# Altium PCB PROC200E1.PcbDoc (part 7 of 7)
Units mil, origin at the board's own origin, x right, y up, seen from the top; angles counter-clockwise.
Board outline 4163.97 x 3505.34 mil, 6 copper layers (Top Layer, GND1, SIG1, PWR, GND2, Bottom), stack 58.132 mil thick; 367 components, 387 nets, 1784 pads, 858 vias.
Unrouted connection lines stored in the file: 17.
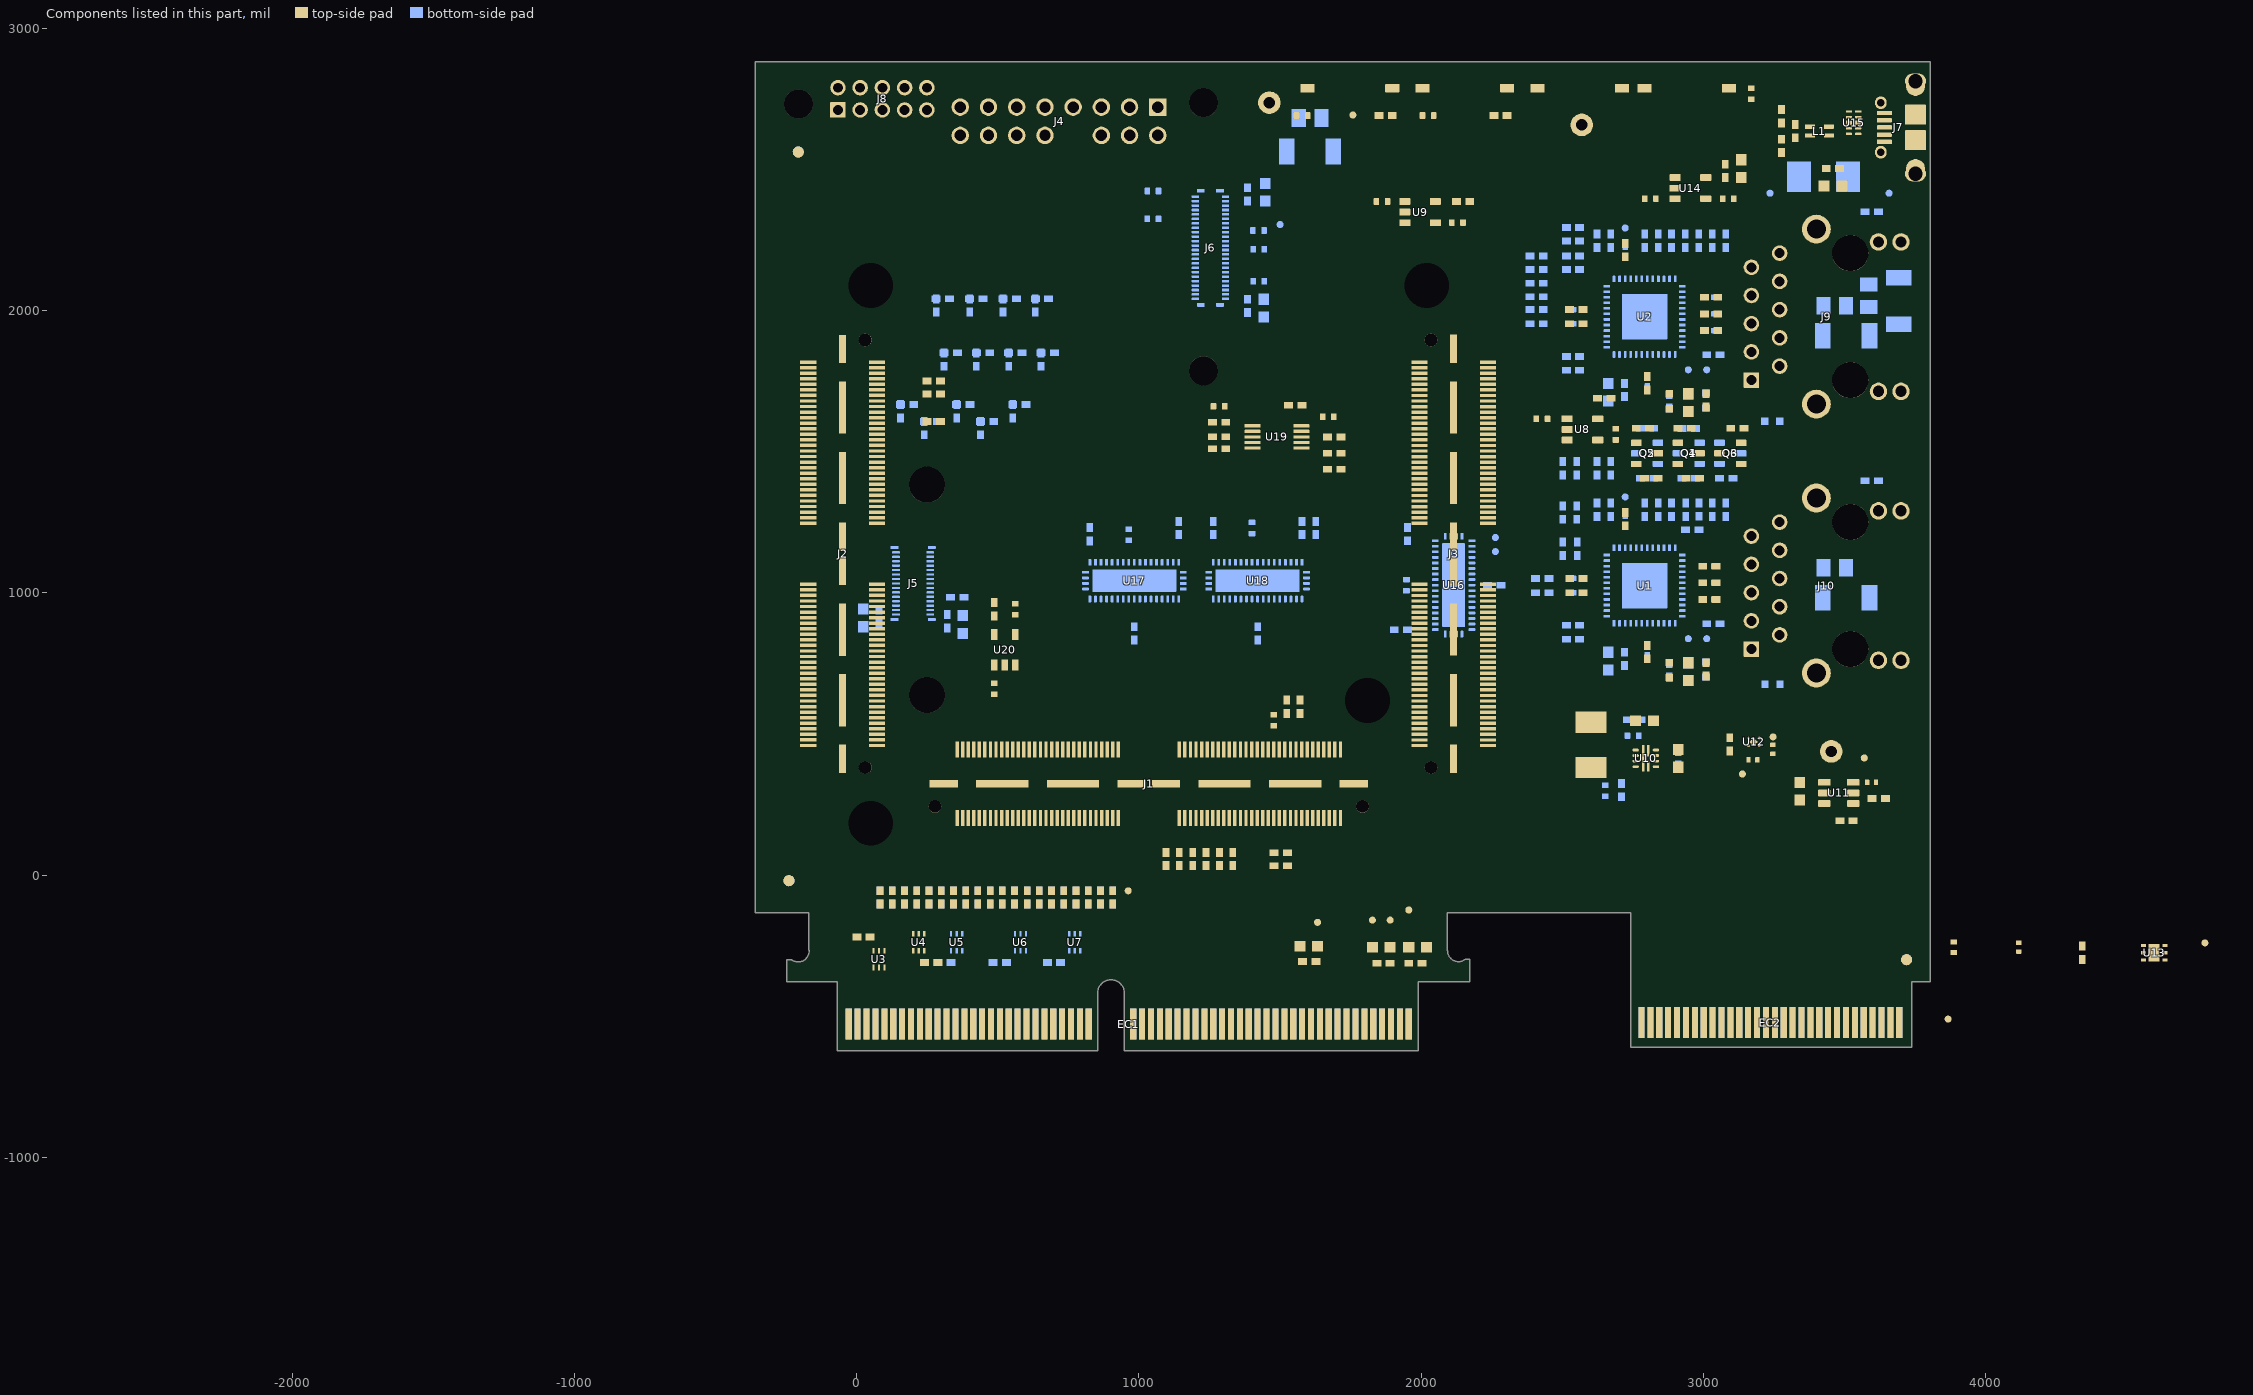
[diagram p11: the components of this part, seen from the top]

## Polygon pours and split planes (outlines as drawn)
GND on PWR "PWR_GND_P156" (solid, remove dead copper, pour order 156): 853.8,-555.76 853.8,-418.09 853.9,-418.09 cw(c901.05,-418.09) 948.19,-418.09 948.29,-418.09 948.29,-550.72 1989.24,-550.72 1989.23,-377.97 2171.95,-377.97 2171.95,-298.97 2155.95,-298.97 cw(c2132.45,-267.85) 2093.45,-267.97 2092.95,-267.97 2092.95,-133.97 2743.26,-133.97 2743.26,-550.72 3738.54,-550.72 3738.54,-377.87 3803.95,-377.87 3803.95,2882.53 -360.02,2882.53 -360.02,-133.97 -169.05,-133.97 -169.05,-266.97 -168.55,-266.95 cw(c-207.5,-268.88) -231.05,-299.97 -247.05,-299.97 -247.05,-377.97 -68.64,-377.97 -68.64,-555.76
VDD_ETH_2V5 on PWR "PWR_VDD_ETH_2V5_P097" (solid, remove dead copper, pour order 97): 2900.95,584.81 2796.86,480.72 2258.57,480.72 2258.57,1196 1817,1196 1817,1934.06 1469,1934.06 1469,2068.71 2114,2068.71 2114,1958.99 2114,1393 2432.71,1393 2432.71,619.35 2865.14,619.35 2865.14,681.93 2900.95,681.93
VMAIN_5V0_IN on PWR "PWR Layer 4-5V0_IN" (solid, remove dead copper, pour order 140): 1828.81,-250.32 1828.81,-128.93 1919.74,-38 2302.9,-38 2777,-38 2777,-450 3711.31,-450 3711.31,-357.25 3731.03,-337.53 3763.61,-337.53 3763.61,2449.57 3724.18,2489 3178,2489 3170,2481 3170,2411 3202.77,2378.23 3738.12,2378.23 3738.12,-202.88 3119.71,-202.88 3119.71,447 2927.37,447 2927.37,380.61 2894.21,347.44 2845.44,347.44 2749.93,251.93 2134.94,251.93 2134.94,798.41 1490,798.41 1490,15 1000,15 558.35,15 558.35,-436.88 727.21,-436.88 727.21,-323.31 692.25,-288.34 692.25,-220 1359.38,-220 1359.38,-462.63 1388.1,-462.63 1388.1,-357.25 1578.89,-357.25 1578.89,-462.64 1608.36,-462.64 1608.36,-357.25 1726.41,-357.25 1795.78,-426.61 1795.78,-462.64 1828.81,-462.64
3V3_LDO2 on PWR "3V3_LDO2_L08_P-001" (solid, remove dead copper, pour order 141): 2795.42,479.28 2900.95,584.81 2900.95,604.05 2916.25,619.35 3101.38,619.35 3305.09,415.64 3305.09,331.82 3299.11,325.84 3135,325.84 3135,443.19 3115.36,462.82 3114.83,462.29 2927.37,462.29 2912.08,447 2912.08,391.63 2883.18,362.73 2839.11,362.73 2738.99,262.62 2123.04,262.62 2123.04,798.14 1475,798.14 1475,512 1384.15,512 1384.15,742 534.08,742 534.08,624 467.49,624 467.49,742 14.72,742 14.72,-177 633.95,-177 633.95,-451.58 713.13,-451.58 713.13,-235.72 964.72,-235.72 1359,-235.72 1359,-478 1862,-478 1862,-99.81 2060.3,-99.81 2060.3,-355.15 1969.72,-355.15 1969.72,-550.72 988.63,-550.72 988.63,-353.09 813.55,-353.09 813.55,-555.76 -68.64,-555.76 -68.64,-393.64 -68.64,-378 -168.55,-378 -168.55,-133.97 -280.28,-133.97 -280.28,479.28 -277.35,482.2 -277.35,978 783,978 783,2382.59 -360.02,2382.59 -360.02,2882.53 3803.95,2882.53 3803.95,2386.29 2327.43,2386.29 2327.43,2073.04 2432.71,2073.04 2432.71,1408.29 2295,1408.29 2295,479.28 2744.36,479.28
VDDIO_3V3 on PWR "VDDIO_3V3_L08_P-001" (solid, remove dead copper, pour order 147): 2338.95,2371 2338.95,2084 2448,2084 2448,634.64 3107.71,634.64 3423.36,319 3713.68,319 3713.68,2371
VBUS_MICRO_AB_5V0 on PWR "PWR-VBUS_MICRO_AB_5V0" (solid, remove dead copper, pour order 130): 3149.78,2608 3187.67,2570.11 3241.84,2570.11 3279.72,2608 3803.95,2608 3803.95,2421 3519,2421 3519,2500 2937,2500 2937,2554 2991,2608
GND on GND1 "GND1_GND_P144" (solid, remove dead copper, pour order 144): 853.8,-555.76 853.8,-418.09 853.9,-418.09 cw(c901.05,-418.09) 948.19,-418.09 948.29,-418.09 948.29,-550.72 1989.24,-550.72 1989.23,-377.97 2171.95,-377.97 2171.95,-298.97 2155.95,-298.97 cw(c2132.45,-267.85) 2093.45,-267.97 2092.95,-267.97 2092.95,-133.97 2743.26,-133.97 2743.26,-550.72 3738.54,-550.72 3738.54,-377.87 3803.95,-377.87 3803.95,2882.53 -360.02,2882.53 -360.02,-133.97 -169.05,-133.97 -169.05,-266.97 -168.55,-266.95 cw(c-207.5,-268.88) -231.05,-299.97 -247.05,-299.97 -247.05,-377.97 -68.64,-377.97 -68.64,-555.76
SHIELD5 on GND1 "GND1_SHIELD5_P142" (solid, remove dead copper, pour order 142): 1625.66,2839.7 1625.66,2516 1747,2516 1747,2668 1849.27,2770.27 3554.37,2770.27 3608.08,2709 3608.08,2066 3803.95,2066 3803.95,2839.7
SHIELD2 on GND1 "GND1_SHIELD2_P143" (solid, remove dead copper, pour order 143): 3349.03,2339.71 3349.03,664.52 3451.39,664.52 3451.39,2339.71
GND on Top Layer "TOP_LAYER_GND_P164" (solid, remove dead copper, pour order 164): 853.8,-555.76 853.8,-418.09 853.9,-418.09 cw(c901.05,-418.09) 948.19,-418.09 948.29,-418.09 948.29,-550.72 1989.24,-550.72 1989.23,-377.97 2171.95,-377.97 2171.95,-298.97 2155.95,-298.97 cw(c2132.45,-267.85) 2093.45,-267.97 2092.95,-267.97 2092.95,-133.97 2743.26,-133.97 2743.26,-550.72 3738.54,-550.72 3738.54,-377.87 3803.95,-377.87 3803.95,2882.53 -360.02,2882.53 -360.02,-133.97 -169.05,-133.97 -169.05,-266.97 -168.55,-266.95 cw(c-207.5,-268.88) -231.05,-299.97 -247.05,-299.97 -247.05,-377.97 -68.64,-377.97 -68.64,-555.76
VDDIO_3V3 on Top Layer "TOP_LAYER_VDDIO_3V3_P145" (solid, remove dead copper, pour order 145): 2471.25,817.61 2582.4,817.61 2620.96,779.05 2770.67,779.05 2789.51,797.89 2813.14,797.89 2823.25,808 3026.4,808 3177.11,657.29 3289.21,657.29 3509,437.5 3509,318.6 3509.05,317.72 3510.18,316.59 3584.75,316.59 3587.87,319.71 3587.87,443.13 3317,714 3186,714 2994.05,905.95 2679.76,905.95 2638.7,947.01 2638.7,1012.36 2557.81,1012.36 2557.81,949 2471.25,949
VMAIN_5V0_IN on Top Layer "TOP_LAYER_VMAIN_5V0_IN_P149" (solid, remove dead copper, pour order 149): 1964.94,740.65 2083,740.65 2083,625 2028.18,625 2028.18,701.28 1964.94,701.28
VDD_ETH_2V5 on Top Layer "TOP_LAYER_VDD_ETH_2V5_P160" (solid, remove dead copper, pour order 160): 2976.87,640 3055,561.87 3055,406 3082,379 3139,379 3151.98,391.98 3151.98,464.89 3151.87,465 3161.72,465 3169.98,456.73 3169.98,359.98 3148,338 3015,338 3001,352 3001,517 2933.19,584.81 2800.15,584.81 2779.69,564.34 2779.69,508.83 2809.59,508.83 2809.59,478 2789.96,478 2779.69,467.72 2779.69,438.09 2751.47,438.09 2696.92,492.64 2547.08,492.64 2547.08,640
NetL2_1 on Top Layer "TOP_LAYER_NETL2_1_P159" (solid, remove dead copper, pour order 159): 2790.91,326.07 2775.36,310.52 2547.08,310.52 2547.08,418.96 2656.28,418.96 2656.28,363.7 2780.51,363.7 2783.04,366.24 2783.04,460.72 2790.91,460.72
VDD_ETH_1V1 on Top Layer "TOP_LAYER_VDD_ETH_1V1_P161" (solid, remove dead copper, pour order 161): 3259.49,642 3121.66,642 3061.66,703 3037,703 3037,603 3224,603 3224,484 3205,465 3194,465 3185.73,456.73 3185.73,452.8 3259.49,452.8
VMAIN_5V0_IN on Top Layer "TOP_LAYER_VMAIN_5V0_IN_P158" (solid, remove dead copper, pour order 158): 2980.62,350.86 2980.62,403.58 2894.21,403.58 2879.5,388.87 2814.84,388.87 2808.63,395.09 2808.63,407.57 2800.76,407.57 2800.76,354.21 2804.1,350.86
VBUS_MICRO_AB_5V0 on Top Layer "TOP_LAYER_VBUS_MICRO_AB_5V0_P157" (solid, remove dead copper, pour order 157): 3466.87,2605.54 3666.58,2605.54 3667.73,2604.39 3667.73,2590.95 3666.58,2589.79 3616.55,2589.79 3593,2566.25 3593,2421 3466.87,2421
SHIELD5 on Top Layer "TOP_LAYER_SHIELD5_P148" (solid, remove dead copper, pour order 148): 3714.19,2839.79 3788.99,2839.79 3788.99,2457.9 3714.19,2457.9
VMAIN_5V0_IN on Top Layer "TOP_LAYER_VMAIN_5V0_IN_P150" (solid, remove dead copper, pour order 150): 1530.95,349.19 1562.64,349.19 1562.64,509.36 1530.95,509.36
VBUS_MICRO_AB_5V0 on Top Layer "TOP_LAYER_VBUS_MICRO_AB_5V0_P153" (solid, remove dead copper, pour order 153): 2880.21,2459.66 2880.21,2550 3022,2550 3022,2500 2919.58,2500 2919.58,2459.66
GND on Bottom "BOTTOM_GND_P162" (solid, remove dead copper, pour order 162): 853.8,-555.76 853.8,-418.09 853.9,-418.09 cw(c901.05,-418.09) 948.19,-418.09 948.29,-418.09 948.29,-550.72 1989.24,-550.72 1989.23,-377.97 2171.95,-377.97 2171.95,-298.97 2155.95,-298.97 cw(c2132.45,-267.85) 2093.45,-267.97 2092.95,-267.97 2092.95,-133.97 2743.26,-133.97 2743.26,-550.72 3738.54,-550.72 3738.54,-377.87 3803.95,-377.87 3803.95,2882.53 -360.02,2882.53 -360.02,-133.97 -169.05,-133.97 -169.05,-266.97 -168.55,-266.95 cw(c-207.5,-268.88) -231.05,-299.97 -247.05,-299.97 -247.05,-377.97 -68.64,-377.97 -68.64,-555.76
SHIELD5 on Bottom "BOTTOM_SHIELD5_P151" (solid, remove dead copper, pour order 151): 1621.2,2534 1636.74,2518.45 1716.39,2518.45 1731.93,2534 1793,2534 3703.64,2534 3714.19,2523.45 3714.19,2212.35 3551,2212.35 3551,2066 3803.95,2066 3803.95,2839.7 1621.2,2839.7
VBUS_MICRO_AB_5V0 on Bottom "BOTTOM_VBUS_MICRO_AB_5V0_P154" (solid, remove dead copper, pour order 154): 3466.87,2529 3593,2529 3593,2421 3466.87,2421
SHIELD2 on Bottom "BOTTOM_SHIELD2_P152" (solid, remove dead copper, pour order 152): 3349.03,664.51 3451.39,664.51 3451.39,2339.71 3349.03,2339.71
GND on GND2 "GND2_GND_P167" (solid, remove dead copper, pour order 167): 853.8,-555.76 853.8,-418.09 853.9,-418.09 cw(c901.05,-418.09) 948.19,-418.09 948.29,-418.09 948.29,-550.72 1989.24,-550.72 1989.23,-377.97 2171.95,-377.97 2171.95,-298.97 2155.95,-298.97 cw(c2132.45,-267.85) 2093.45,-267.97 2092.95,-267.97 2092.95,-133.97 2743.26,-133.97 2743.26,-550.72 3738.54,-550.72 3738.54,-377.87 3803.95,-377.87 3803.95,2882.53 -360.02,2882.53 -360.02,-133.97 -169.05,-133.97 -169.05,-266.97 -168.55,-266.95 cw(c-207.5,-268.88) -231.05,-299.97 -247.05,-299.97 -247.05,-377.97 -68.64,-377.97 -68.64,-555.76
SHIELD2 on GND2 "GND2_SHIELD2_P166" (solid, remove dead copper, pour order 166): 3349.03,2339.71 3349.03,664.52 3451.39,664.52 3451.39,2339.71
SHIELD5 on GND2 "GND2_SHIELD5_P165" (solid, remove dead copper, pour order 165): 1625.66,2839.7 1625.66,2516 1747,2516 1747,2668 1849.27,2770.27 3554.37,2770.27 3608.08,2709 3608.08,2066 3803.95,2066 3803.95,2839.7
GND on SIG1 "SIG1_GND_P163" (solid, remove dead copper, pour order 163): 853.8,-555.76 853.8,-418.09 853.9,-418.09 cw(c901.05,-418.09) 948.19,-418.09 948.29,-418.09 948.29,-550.72 1989.24,-550.72 1989.23,-377.97 2171.95,-377.97 2171.95,-298.97 2155.95,-298.97 cw(c2132.45,-267.85) 2093.45,-267.97 2092.95,-267.97 2092.95,-133.97 2743.26,-133.97 2743.26,-550.72 3738.54,-550.72 3738.54,-377.87 3803.95,-377.87 3803.95,2882.53 -360.02,2882.53 -360.02,-133.97 -169.05,-133.97 -169.05,-266.97 -168.55,-266.95 cw(c-207.5,-268.88) -231.05,-299.97 -247.05,-299.97 -247.05,-377.97 -68.64,-377.97 -68.64,-555.76

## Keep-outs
Top Layer:
  lines w6: 2539.68,432.68 2539.68,489.28
Keep-Out Layer:
  circle w4: c248.97,1383.25 r97.98
  circle w4: c248.97,637.58 r97.98
  circle w4: c-206.55,2731.73 r86
  circle w4: c1228.45,2736.73 r86
  circle w4: c1228.45,1786.73 r86
  circle w4: c49.98,183.39 r120
  circle w4: c29.9,1895.87 r40
  circle w4: c2019.98,2088.39 r120
  circle w4: c49.98,2088.39 r120
  circle w4: c29.9,380.91 r40
  circle w4: c2035.06,1895.87 r40
  circle w4: c277.5,243.47 r40
  region: 1752.46,243.47 ccw(c1792.46,243.47) 1792.46,203.47 ccw(c1792.46,243.47) 1832.46,243.47 ccw(c1792.46,243.47) 1792.46,283.47 ccw(c1792.46,243.47)
  region: 1995.06,380.91 ccw(c2035.06,380.91) 2035.06,340.91 ccw(c2035.06,380.91) 2075.06,380.91 ccw(c2035.06,380.91) 2035.06,420.91 ccw(c2035.06,380.91)
  region: 1689.98,618.39 ccw(c1809.98,618.39) 1809.98,498.39 ccw(c1809.98,618.39) 1929.98,618.39 ccw(c1809.98,618.39) 1809.98,738.39 ccw(c1809.98,618.39)
  text ".Layer_Name" at -423.89,-2614.75 h60

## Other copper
Top Layer:
  text ".Layer_Name" at -423.89,-2614.75 h60
SIG1:
  text ".Layer_Name" at -340,-2596 h60
GND1:
  text ".Layer_Name" at -258.03,-2598.97 h60
GND2:
  text ".Layer_Name" at -258.03,-2598.97 h60
PWR:
  text ".Layer_Name" at -232,-2649 h60
Bottom:
  text ".Layer_Name" at -348.89,-2605.75 h60

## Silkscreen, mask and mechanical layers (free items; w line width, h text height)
Top Overlay:
  text ".Layer_Name" at -423.89,-2619.76 h60
Bottom Overlay:
  rectangle: 730.44,579.94 1418.32,678.03
  lines w10: 1373.32,439.8 1373.32,538.03 ; 1418.32,579.8 1418.32,678.03 ; 1556.62,679.94 730.44,679.94 730.44,579.94 1556.62,579.94 1556.62,680.09 ; 685.44,439.94 1599,439.94 1599,539.94 685.44,539.94 685.44,439.94
  text "PROC200E1" at 455.51,2448 h90
  text "HSEC180ADAPEVM-AM2" at 706.15,2328 h90
  text "SL#" at 1541.21,608.3 h70
  text "ASSY#" at 1589,470 h70
  text "PROC200E1-001" at 1340,463.6 h90
  text ".Layer_Name" at 2051,-2648 h60
Top Paste:
  text ".Layer_Name" at -423.89,-2619.76 h60
Bottom Paste:
  text ".Layer_Name" at -416.89,-2615.75 h60
Top Solder:
  lines w50: -70.05,-377.97 -70.05,-613.97 852.06,-613.97 852.06,-416.97 cw(c899.06,-416.97) 946.06,-416.97 946.06,-613.97 1994.95,-613.97 1994.95,-377.97 ; 2743.26,-453.09 2743.26,-609.97 3738.54,-609.97 3738.54,-377.87
  text ".Layer_Name" at -423.89,-2619.76 h60
  text ".Layer_Name" at -423.89,-2619.76 h60
Bottom Solder:
  lines w50: -70.05,-377.97 -70.05,-613.97 852.06,-613.97 852.06,-416.97 cw(c899.06,-416.97) 946.06,-416.97 946.06,-613.97 1994.95,-613.97 1994.95,-377.97 ; 2743.26,-453.09 2743.26,-609.97 3738.54,-609.97 3738.54,-377.87
  text ".Layer_Name" at 2148,-2670 h60
Drill Guide:
  text ".Layer_Name" at -423.89,-2614.75 h60
M1 Board Outline:
  lines w10: -169.05,-266.97 -169.05,-133.97 -360.02,-133.97 -360.02,2882.53 3803.95,2882.53 3803.95,-377.87 3738.54,-377.87 3738.54,-609.97 2743.26,-609.97 2743.26,-133.97 2092.95,-133.97 2092.95,-170.38 2092.95,-267.97 ; -168.55,-266.95 cw(c-207.5,-268.88) -231.05,-299.97 -247.05,-299.97 -247.05,-377.97 -68.64,-377.97 -68.64,-622.81 853.8,-622.81 853.8,-418.09 ; 853.9,-418.09 cw(c901.05,-418.09) 948.19,-418.09 ; 948.29,-418.09 948.29,-622.81 1989.24,-622.81 1989.23,-377.97 1994.95,-377.97 2171.95,-377.97 2171.95,-298.97 2155.95,-298.97 cw(c2132.45,-267.85) 2093.45,-267.97
  text ".Layer_Name" at -430,-2560 h60
M2 Board Dimensions:
  lines w10: 5007.95,974.01 5075.95,974.01 ; 5049.95,945.01 5076.95,973.01 ; 5049.95,1004.01 5076.95,974.01 ; 5083.95,2319.01 5151.95,2401.01 ; 5085.95,927.01 5085.95,1249.01 ; 5085.95,1290.01 5135.95,1236.01 5245.95,1236.01 5292.95,1293.01 ; 5085.95,1292.01 5085.95,2322.01 ; 5150.95,2402.01 5214.95,2315.01 ; 5168.95,1142.01 5236.95,1142.01 ; 5210.95,1113.01 5237.95,1141.01 ; 5210.95,1172.01 5237.95,1142.01 ; 5215.95,2314.01 5287.95,2404.01 ; 5246.95,927.01 5246.95,1209.01 ; 5292.95,1292.01 5292.95,2322.01 5292.95,2407.01 ; 5293.95,927.01 5293.95,1249.01 ; 5299.92,1942.63 cw(c5243.95,1235.01) 5683.29,1792.54 ; 5301.8,1941.26 ccw(c5441.55,2175.92) 5352.67,1917.67 ; 5301.95,977.01 5328.95,947.01 ; 5301.95,978.01 5328.95,1006.01 ; 5301.95,1948.01 cw(c5334.4,1774.03) 5364.67,1948.4 ; 5303.95,978.01 5371.95,978.01 ; 5303.95,1141.01 5330.95,1111.01 ; 5303.95,1142.01 5330.95,1170.01 ; 5305.95,1142.01 5373.95,1142.01 ; 5319.95,1331.01 5782.95,1903.01 ; 5629.95,1807.01 ccw(c5767.48,2147.44) 5684.61,1789.75 ; 5647.2,1840.31 cw(c5530.34,1706.86) 5685.95,1792
  text "30" at 5488.95,1963.01 h60
  text "18MIL" at 5414.95,1114.01 h60
  text "62MIL" at 5407.95,950.01 h60
  text "GOLD FINGER" at 4926.95,713.01 h60
  text "SIDE VIEW" at 4980.95,600.01 h60
  text ".Layer_Name" at -423.89,-2614.75 h60
M3 3D STEP Top:
  text ".Layer_Name" at -423.89,-2619.76 h60
M4 3D STEP Bottom:
  drawing of 3742 lines, arcs and shapes, not listed
  text ".Layer_Name" at -416.89,-2615.75 h60
M5 Assembly Top:
  lines w4: -232.55,-338.47 3708.02,-338.47
  lines w6: -70.05,-555.16 1989.23,-555.16 ; 2743.26,-609.97 2743.26,-19.42 3333.81,-19.42 ; 3803.95,1344.63 3803.95,1659.59 3948.44,1659.59
  lines w10: -1292.89,-2691.43 5307.11,-2691.43 ; -1292.89,-2488.1 5309.11,-2488.1 ; -1292.89,-2284.76 -1292.89,-2894.76 2712.11,-2894.76 5309.11,-2894.76 5309.11,-2284.76 -1292.39,-2284.76 -1292.39,-2894.76 283.11,-2894.76 ; 1172.11,-2894.76 1172.11,-2284.76 ; 2439.11,-2488.1 2439.11,-2284.76 ; 3279.11,-2488.1 3279.11,-2284.76 ; 3901.11,-2901.26 3901.11,-2698.43
  text "ASSEMBLY VARIANT:" at 152.11,-2195.26 h60
  text ".VariantName" at 1188.11,-2195.26 h60
  text "PCB VIEWED FROM TOP SIDE" at -1229.39,-2416.93 h60
  text "BOARD #:" at 1247.11,-2416.93 h60
  text ".PRJ_Number" at 1792.61,-2416.93 h60
  text "REV:" at 2637.11,-2416.93 h60
  text ".PCB_Rev" at 2928.61,-2416.93 h60
  text "SVN REV:" at 3475.11,-2416.93 h60
  text ".VersionControl_RevNumber" at 3981.11,-2416.93 h60
  text ".TID" at -627.39,-2560.26 h60
  text "TID #:" at -1089,-2612 h60
  text "GENERATED    :" at -1170.89,-2765.59 h60
  text "PLOT NAME =" at -1229.39,-2825.6 h60
  text ".plot_File_Name" at -423.89,-2825.6 h60
  text ".Print_Date" at 2118.61,-2825.6 h60
  text ".Print_Time" at 2847.61,-2825.6 h60
  text "TEXAS INSTRUMENTS" at 4112.11,-2825.6 h60
M6 Assembly Bottom:
  lines w10: -1286.39,-2484.59 5315.61,-2484.59 ; -1284.39,-2687.92 5315.61,-2687.92 ; 121.61,-2897.76 121.61,-2694.92 ; 743.61,-2484.59 743.61,-2281.26 ; 1583.61,-2484.59 1583.61,-2281.26 ; 2850.61,-2891.26 2850.61,-2281.26 ; 3739.61,-2891.26 5315.11,-2891.26 5315.11,-2281.26 -1286.39,-2281.26 -1286.39,-2891.26 1310.61,-2891.26 5315.61,-2891.26 5315.61,-2281.26
  text "COMPONENTS MARKED 'DNP' SHOULD NOT BE POPULATED." at 5108.11,-2075.26 h60
  text ".VariantName" at 4064.11,-2191.26 h60
  text "ASSEMBLY VARIANT:" at 5103.11,-2191.26 h60
  text ".VersionControl_RevNumber" at 41.61,-2413.42 h60
  text "SVN REV:" at 547.61,-2413.42 h60
  text ".PCB_Rev" at 1094.11,-2413.42 h60
  text "REV:" at 1385.61,-2413.42 h60
  text ".PRJ_Number" at 2230.11,-2413.42 h60
  text "BOARD #:" at 2775.61,-2413.42 h60
  text "PCB VIEWED FROM BOTTOM SIDE" at 5252.11,-2413.42 h60
  text ".TID" at 2230.11,-2616.76 h60
  text "TID #:" at 2775.61,-2616.76 h60
  text "TEXAS INSTRUMENTS" at -89.39,-2822.09 h60
  text ".Print_Time" at 1175.11,-2822.09 h60
  text ".Print_Date" at 1904.11,-2822.09 h60
  text "GENERATED    :" at 2773.61,-2822.09 h60
  text ".plot_File_Name" at 4446.61,-2822.09 h60
  text "PLOT NAME =" at 5252.11,-2822.09 h60
M9 Title Sheet:
  drawing of 57 lines, arcs and shapes, not listed
  text "1" at -261.06,6280.24 h70
  text "2" at 2234.61,6280.24 h70
  text "3" at 4723.95,6280.24 h70
  text "4" at 7230.62,6280.24 h70
  text "5" at 9729.61,6280.24 h70
  text "6" at 12234.61,6280.24 h70
  text "A" at -1417.39,5137.24 h70
  text "A" at 13382.61,5137.24 h70
  text "B" at -1417.39,2757.24 h70
  text "B" at 13382.61,2757.24 h70
  text "C" at -1417.39,382.24 h70
  text "C" at 13382.61,382.24 h70
  text "PROJECT TITLE:" at 10342.61,-1478.76 h45
  text ".PRJ_Title" at 10392.61,-1612.08 h70
  text "DESIGNED FOR:" at 10342.61,-1779.76 h45
  text ".PRJ_Customer" at 10392.61,-1919.76 h70
  text "D" at -1417.39,-1987.76 h70
  text "D" at 13382.61,-1987.76 h70
  text "FILE NAME:" at 10342.61,-2079.76 h45
  text ".PCB_File_Name_No_Path" at 10392.61,-2199.76 h70
  text "Texas Instruments (TI) and/or its licensors do not warrant the accuracy or completeness of this specification" at 5373.11,-2361.6 h45
  text "ENGINEER:" at 10342.61,-2369.76 h45
  text "LAYOUT BY:" at 11847.61,-2369.76 h45
  text "or any information contained therein. TI and/or its licensors do not warrant that this design will meet" at 5328.12,-2474.26 h45
  text ".PRJ_Engineer" at 10392.61,-2524.75 h70
  text ".PCB_Layout" at 11898.11,-2524.75 h70
  text "the specifications, will be suitable for your application or fit for any particular purpose, or will operate in" at 5328.12,-2586.93 h45
  text ".Layer_Name" at -423.89,-2614.75 h60
  text "ALTIUM DESIGNER VERSION:" at 11847.61,-2679.76 h45
  text "an implementation. TI and/or its licensors do not warrant that the design is production worthy. You should" at 5328.12,-2699.59 h45
  text "completely validate and test your design implementation to confirm the system functionality for your application." at 5373.11,-2812.26 h45
  text ".print_Scale" at 10392.61,-2813.08 h70
  text ".Application_BuildNumber" at 11898.11,-2813.08 h70
  text "1" at -261.06,-3019.76 h70
  text "2" at 2234.61,-3019.76 h70
  text "3" at 4723.95,-3019.76 h70
  text "4" at 7230.62,-3019.76 h70
  text "5" at 9729.61,-3019.76 h70
  text "6" at 12234.61,-3019.76 h70
M10 Fab Notes:
  drawing of 182 lines, arcs and shapes, not listed
  text "J5 and J11: NPTH on SMT pads are intentional per manufacturers footprint.  SMT pad copper may be pulled back 5-8Mil from holes as needed for processing." at 7180,5027 h59
  text "DESIGN INFORMATION" at 11381.13,4739.92 h60
  text "4" at 11834.97,4611.03 h60
  text "MIN. TRACK WIDTH:" at 10736.57,4607.79 h60
  text "MIL" at 11987.57,4607.79 h60
  text "4.5" at 11785,4489 h60
  text "MIN. CLEARANCE:" at 10736.57,4483.66 h60
  text "MIL" at 11987.57,4483.66 h60
  text "MIN. VIA PAD SIZE:" at 10736.57,4359.54 h60
  text "18" at 11802.82,4359.54 h60
  text "MIL" at 11987.57,4359.54 h60
  text "0.05mm (2MIL)" at 11431.57,4229.64 h60
  text "MINIMUM ANNULAR RING" at 10407.34,4221.42 h60
  text "EXTERNAL" at 12139.57,4221.42 h60
  text "PER" at 10607.34,4111.29 h60
  text "IPC-D-275 CLASS 2 LEVEL C" at 10827.34,4111.29 h60
  text "MIL, HOLES" at 12315.57,4010.81 h60
  text "+/-" at 11923.11,4002.23 h60
  text "+/-" at 12777.11,4002.23 h60
  text "REGISTRATION TOLERANCES:" at 10407.34,4001.16 h60
  text "METAL" at 11607.11,4001.16 h60
  text "5" at 12183.31,4001.16 h60
  text "3" at 13016.31,4001.16 h60
  text "MIL" at 13132.57,4001.16 h60
  text "SCALE : NTS" at 240,3960 h80
  text "HOLE SIZE TOLERANCE (UNLESS OTHERWISE SPECIFIED):" at 10407.34,3902.85 h60
  text "+/-" at 12777.11,3899.97 h60
  text "3" at 13016.31,3898.91 h60
  text "MIL" at 13132.57,3898.91 h60
  text "NOTES:" at -960.66,3809.41 h60
  text "MATERIAL:" at 10332.57,3761.26 h60
  text "1. BOARD SHALL MEET THE REQUIREMENTS OF UL-796E WITH FLAMMABILITY RATING OF MINIMUM 94V-0. UL LOGO," at -933.91,3663.59 h60
  text "FR-4 High Tg" at 11319.01,3632.74 h60
  text "X" at 11174.57,3624.75 h60
  text "FR-408" at 10753.57,3620.23 h60
  text "OTHER" at 12241.57,3620.23 h60
  text "MANUFACTURER'S IDENTIFICATION AND DATE CODE LETTER SHALL BE RENDERED IN SILKSCREEN." at -827.18,3564.59 h60
  text "62 MIL (1.6mm) +/-10%" at 11073.67,3477.2 h60
  text "X" at 10953.57,3474.75 h60
  text "THICKNESS:" at 10407.34,3468.98 h60
  text "OTHER" at 12358.57,3468.98 h60
  text "2. VENDOR MAY ADJUST SOLDERMASK WHEREVER SOLDERMASK PADS ARE THE SAME SIZE (1:1) AS PER THE MANUFACTURING CAPABILITIES" at -940.9,3438.81 h60
  text "AND ALL OTHER SOLDER MASK PADS SHALL NOT BE MODIFIED, PROVIDED NO ADJACENT COPPER IS EXPOSED AND NO CONFLICT IS PRODUCED" at -834.17,3339.81 h60
  text "TOLERANCE:" at 10407.34,3330.67 h60
  text "X" at 11255.57,3330.67 h60
  text "ANSI IPC-6012 TYPE 3 CLASS 2" at 11433.58,3330.67 h60
  text "WITH ANY STATED \"VIA TENTING/COVERING\" REQUIREMENTS." at -834.17,3246.52 h60
  text "OTHER +/-" at 11433.57,3186.48 h60
  text "3. MANUFACTURER'S IDENTIFICATION,DATECODE LETTER SHALL BE SILKSCREENED ON SOLDER SIDE OF THE BOARD." at -937.22,3128.43 h60
  text "BOW & TWIST:" at 10407.34,3041.29 h60
  text "X" at 11255.57,3041.29 h60
  text "ANSI IPC-6012 TYPE 3 CLASS 2" at 11433.58,3041.29 h60
  text "4. LAYER TO LAYER REGISTRATION SHALL BE WITHIN +/-2 MIL." at -937.22,2959.33 h60
  text "OTHER +/-" at 11433.57,2894.59 h60
  text "5. REFER IMPEDANCE TABLE FOR IMPEDANCE CONTROL TRACES ON LAYER 1, 3 & 6." at -937.22,2793.46 h60
  text "DRILLING:" at 10332.57,2763.97 h60
  text "NC_DRILL FILES" at 12093.57,2658.78 h60
  text "REFERENCE:" at 10407.34,2654.85 h60
  text "X" at 11064.57,2654.75 h60
  text "AS SHOWN" at 11242.57,2654.85 h60
  text "X" at 11965.57,2654.85 h60
  text "6. ALL VIAS ARE TENTED ON BOTH SIDES UNLESS OTHERWISE SOLDER MASK OPENED IN GERBER." at -937.22,2633.31 h60
  text "OTHER" at 12391.57,2512.59 h60
  text "PTH COPPER THICKNESS:" at 10407.01,2509.07 h60
  text "X" at 11546.25,2509.07 h60
  text "20-30 um" at 11674.24,2509.07 h60
  text "BOARD FINISH:" at 10332.57,2361.47 h60
  text "SILKSCREEN:" at 10487.79,2251.34 h60
  text "X" at 11445.57,2251.34 h60
  text "TOP" at 11562.57,2251.34 h60
  text "X" at 11955.57,2251.34 h60
  text "BOTTOM" at 12073.57,2251.34 h60
  text "SILKSCREEN COLOR:" at 10487.79,2096.15 h60
  text "X" at 11444.57,2096.15 h60
  text "WHITE" at 11562.57,2096.15 h60
  text "OTHER" at 12073.57,2096.15 h60
  text "BLUE" at 12728.57,1962.71 h60
  text "GREEN" at 11693.57,1952.71 h60
  text "OTHER" at 12311.57,1952.71 h60
  text "X" at 11575,1950 h60
  text "SOLDER RESIST COLOR:" at 10487.79,1945.84 h60
  text "MATTE" at 11693.57,1798.45 h60
  text "SEMI-GLOSS" at 12311.11,1797.82 h60
  text "X" at 12163,1795 h60
  text "IMMERSION GOLD (ENIG)" at 11393.57,1625.68 h60
  text "ENEPIG" at 12731.11,1618.46 h60
  text "SURFACE FINISH:" at 10332.57,1617.46 h60
  text "X" at 11215.57,1617.46 h60
  text "IMM. TIN/SILVER OR EQUIV" at 10662.11,1480.15 h60
  text "HARD GOLD OVER NICKEL 30u/80u, ON EDGEFINGERS" at 11036.53,1327.14 h60
  text "X" at 10505.57,1317.46 h60
  text "OTHER" at 10683.57,1316.21 h60
  text "ARRAY/PANEL:" at 10332.57,1180.83 h60
  text "X" at 11212,1175 h60
  text "CUT AND TRIM PER M1 BOARD OUTLINE" at 11393.57,1172.61 h60
  text "N.C. ROUTE" at 11393.57,1036.64 h60
  text "V. SCORE" at 12259.57,1036.64 h60
  text "CERTIFICATION:" at 10332.57,907.52 h60
  text "MATERIALS AND WORKMANSHIP FOR ALL PCBS" at 11057.57,907.52 h60
  text "TO MEET OR EXCEED THE REQUIREMENTS OF:" at 11057.57,813.45 h60
  text "X" at 10693,685 h60
  text "ANSI IPC-A-600F CLASS ->" at 10823.07,684.82 h60
  text "X" at 12471.08,684.82 h60
  text "2" at 12581.07,684.82 h60
  text "1" at 12266.07,683.33 h60
  text "3" at 12935.07,683.33 h60
  text "X" at 11507.08,537.14 h60
  text "RoHS" at 11635.07,537.14 h60
  text "OTHER" at 12279.47,537.14 h60
  text "PER ORDER" at 12676.53,537.14 h60
  text "ALL BOARDS MUST MEET OR EXCEED UL94-V0 REQUIREMENTS." at 10360.11,383.31 h60
  text "PCB MUST BEAR THE UL94V-0 UL REGISTERED MATERIAL ID NUMBER" at 10360.11,267.25 h60
  text "ADDITIONAL REQUIREMENTS:" at 10332.57,97.82 h60
  text "REQUIRED" at 12114.57,-23.64 h60
  text "BARE BOARD ELEC. TEST:" at 10347.34,-26.49 h60
  text "NONE" at 11653.07,-26.49 h60
  text "X" at 12589.11,-26.26 h60
  text "PER ORDER" at 12706.57,-26.49 h60
  text "OUTER LAYERS 6 MIL WIDE, 6 MIL SPACE / TRACES REQUIRE 100 OHM DIFFERENTIAL IMPEDANCE" at 10584.18,-328.19 h60
  text "INNER LAYERS 5 MIL WIDE, 7 MIL SPACE / TRACES REQUIRE 100 OHM DIFFERENTIAL IMPEDANCE" at 10554.18,-513.19 h60
  text "OUTER LAYERS 6.1 MIL WIDE, 6 MIL SPACE / TRACES REQUIRE 90 OHM DIFFERENTIAL IMPEDANCE" at 10566.5,-699.04 h60
  text ".Layer_Name" at -423.89,-2614.75 h60
M11 Gerber Information:
  lines w10: -1292.89,-2686.42 5307.11,-2686.42 ; -1292.89,-2483.09 5309.11,-2483.09 ; -1292.89,-2279.76 -1292.89,-2889.76 2712.11,-2889.76 5309.11,-2889.76 5309.11,-2279.76 -1292.39,-2279.76 -1292.39,-2889.76 283.11,-2889.76 ; 1172.11,-2889.76 1172.11,-2279.76 ; 2439.11,-2483.09 2439.11,-2279.76 ; 3279.11,-2483.09 3279.11,-2279.76 ; 3901.11,-2896.26 3901.11,-2693.42
  text "ALL ARTWORK VIEWED FROM TOP SIDE" at -1229.39,-2411.92 h60
  text "BOARD #:" at 1247.11,-2411.92 h60
  text ".PRJ_Number" at 1792.61,-2411.92 h60
  text "REV:" at 2637.11,-2411.92 h60
  text ".PCB_Rev" at 2928.61,-2411.92 h60
  text "SVN REV:" at 3475.11,-2411.92 h60
  text ".VersionControl_RevNumber" at 3981.11,-2411.92 h60
  text "LAYER NAME =" at -1229.39,-2614.75 h60
  text "TID #:" at 1247.11,-2615.26 h60
  text ".TID" at 1792.61,-2615.26 h60
  text "PLOT NAME =" at -1229.39,-2820.59 h60
  text ".plot_File_Name" at -423.89,-2820.59 h60
  text "GENERATED    :" at 1249.11,-2820.59 h60
  text ".Print_Date" at 2118.61,-2820.59 h60
  text ".Print_Time" at 2847.61,-2820.59 h60
  text "TEXAS INSTRUMENTS" at 4112.11,-2820.59 h60
M12 Stackup:
  drawing of 466 lines, arcs and shapes, not listed
  text "6" at 7956.34,3176.61 h60
  text "IMPEDANCE TABLE :" at 6799.95,3161.23 h80
  text "LAYER" at 6340.22,2971.58 h70
  text "TRACE WIDTH" at 6627.42,2970.73 h70
  text "SPACING" at 7112.42,2970.73 h70
  text "IMPEDANCE +/- 10%" at 7447.42,2970.73 h70
  text "REFERENCE LAYER" at 8172.42,2970.73 h70
  text "-" at 7235,2800 h65
  text "5.66 MILS" at 6686.1,2794.75 h65
  text "LAYER-2 (GND LAYER)" at 8133.83,2794.75 h65
  text "TOP" at 6365,2785 h70
  text "50 OHM" at 7637,2785 h65
  text "LAYER-2 (GND LAYER)" at 8133.83,2612.55 h65
  text "4 MILS" at 6686.1,2607 h65
  text "7 MILS" at 7167,2606 h65
  text "TOP" at 6370,2595 h70
  text "100 OHM" at 7620,2592 h65
  text "LAYER-2 (GND LAYER)" at 8133.83,2426.55 h65
  text "5 MILS" at 6686.1,2425.86 h65
  text "90 OHM" at 7643,2421 h65
  text "TOP" at 6370,2420 h60
  text "6.22 MILS" at 7127,2420 h65
  text "6.66  MILS" at 6686.1,2236 h65
  text "50 OHM" at 7626,2236 h65
  text "L3" at 6395,2235 h60
  text "-" at 7240,2235 h65
  text "LAYER-2 / LAYER-4" at 8133.83,2226.55 h65
  text "4.2  MILS" at 6686.1,2062 h65
  text "L3" at 6385,2060 h60
  text "100 OHM" at 7612,2054 h65
  text "6 MILS" at 7158,2052 h65
  text "LAYER-2 / LAYER-4" at 8133.83,2051.55 h65
  text "-" at 7225,1895 h65
  text "LAYER-5(GND LAYER)" at 8133.83,1890 h65
  text "BOTTOM" at 6312.67,1877.48 h60
  text "5.66 MILS" at 6686.1,1876 h65
  text "50 OHM" at 7626,1869 h65
  text "LAYER-5(GND LAYER)" at 8133.83,1710 h65
  text "7 MILS" at 7152,1705 h65
  text "BOTTOM" at 6315.67,1701.48 h60
  text "4 MILS" at 6686.1,1702 h65
  text "100 OHM" at 7606,1696 h65
  text "LAYER-5(GND LAYER)" at 8133.83,1535 h65
  text "BOTTOM" at 6315.67,1530.25 h60
  text "6.22 MILS" at 7124.35,1530.86 h65
  text "90 OHM" at 7612,1528 h65
  text "5 MILS" at 6686.1,1527 h65
  text "Layer" at 5093.58,44 h60
  text "Name" at 5503.49,44 h60
  text "Material" at 6433.23,44 h60
  text "Thickness" at 7293,44 h60
  text "Constant" at 7942.84,44 h60
  text "Board Layer Stack" at 8512.7,44 h60
  text "Top Overlay" at 5503.49,-76 h60
  text "Top Solder" at 5503.49,-196 h60
  text "Solder Resist" at 6433.23,-196 h60
  text "2.00mil" at 7293,-196 h60
  text "3.6" at 7942.84,-196 h60
  text "1" at 5093.58,-316 h60
  text "Top Layer" at 5503.49,-316 h60
  text "1.85mil" at 7293,-316 h60
  text "Dielectric 1" at 5503.49,-436 h60
  text "FR-4" at 6433.23,-436 h60
  text "3.70mil" at 7293,-436 h60
  text "4.1" at 7942.84,-436 h60
  text "2" at 5093.58,-556 h60
  text "GND1" at 5503.49,-556 h60
  text "1.26mil" at 7293,-556 h60
  text "Dielectric 2" at 5503.49,-676 h60
  text "FR-4" at 6433.23,-676 h60
  text "5.00mil" at 7293,-676 h60
  text "3.7" at 7942.84,-676 h60
  text "3" at 5093.58,-796 h60
  text "SIG1" at 5503.49,-796 h60
  text "1.26mil" at 7293,-796 h60
  text "Dielectric 3" at 5503.49,-916 h60
  text "FR-4" at 6433.23,-916 h60
  text "32.00mil" at 7293,-916 h60
  text "3.7" at 7942.84,-916 h60
  text "4" at 5093.58,-1036 h60
  text "PWR" at 5503.49,-1036 h60
  text "1.26mil" at 7293,-1036 h60
  text "Dielectric 4" at 5503.49,-1156 h60
  text "FR-4" at 6433.23,-1156 h60
  text "5.00mil" at 7293,-1156 h60
  text "3.7" at 7942.84,-1156 h60
  text "5" at 5093.58,-1276 h60
  text "GND2" at 5503.49,-1276 h60
  text "1.26mil" at 7293,-1276 h60
  text "Dielectric 5" at 5503.49,-1396 h60
  text "FR-4" at 6433.23,-1396 h60
  text "3.70mil" at 7293,-1396 h60
  text "4.1" at 7942.84,-1396 h60
  text "6" at 5093.58,-1516 h60
  text "Bottom" at 5503.49,-1516 h60
  text "1.85mil" at 7293,-1516 h60
  text "Bottom Solder" at 5503.49,-1636 h60
  text "Solder Resist" at 6433.23,-1636 h60
  text "2.00mil" at 7293,-1636 h60
  text "3.6" at 7942.84,-1636 h60
  text "Bottom Overlay" at 5503.49,-1756 h60
  text ".Layer_Name" at -423.89,-2614.75 h60
M13 Component Bodies Top:
  text ".Layer_Name" at -423.89,-2619.76 h60
M14 Component Bodies Bottom:
  text ".Layer_Name" at -416.89,-2615.75 h60
M15 Courtyards Top:
  text ".Layer_Name" at -423.89,-2619.76 h60
M16 Courtyards Bottom:
  text ".Layer_Name" at -416.89,-2615.75 h60
Drill Drawing:
  drawing of 183 lines, arcs and shapes, not listed
  text "Symbol" at -837.5,7019.94 h72
  text "Count" at -331.62,7019.94 h72
  text "Hole Size" at 268.22,7019.94 h72
  text "Plated" at 1417.88,7019.94 h72
  text "Hole Tolerance (+)" at 1923.76,7019.94 h72
  text "Hole Tolerance (-)" at 3257.36,7019.94 h72
  text "Hole Length" at 4590.97,7019.94 h72
  text "Routed Path Length" at 5690.65,7019.94 h72
  text "75" at -136.69,6869.94 h60
  text "7.87mil (0.200mm)" at 323.2,6869.94 h60
  text "PTH" at 1417.88,6869.94 h60
  text "-" at 4590.97,6869.94 h60
  text "-" at 5690.65,6869.94 h60
  text "A" at -866.59,6859.95 h66.67
  text "729" at -166.68,6719.94 h60
  text "8.00mil (0.203mm)" at 323.2,6719.94 h60
  text "PTH" at 1417.88,6719.94 h60
  text "3.00mil (0.076mm)" at 2070.71,6719.94 h60
  text "3.00mil (0.076mm)" at 3257.36,6719.94 h60
  text "-" at 4590.97,6719.94 h60
  text "-" at 5690.65,6719.94 h60
  text "52" at -136.69,6569.94 h60
  text "12.00mil (0.305mm)" at 298.21,6569.94 h60
  text "PTH" at 1417.88,6569.94 h60
  text "3.00mil (0.076mm)" at 2070.71,6569.94 h60
  text "3.00mil (0.076mm)" at 3257.36,6569.94 h60
  text "-" at 4590.97,6569.94 h60
  text "-" at 5690.65,6569.94 h60
  text "2" at -106.7,6419.94 h60
  text "25.59mil (0.650mm)" at 293.21,6419.94 h60
  text "PTH" at 1417.88,6419.94 h60
  text "29.53mil (0.750mm)" at 4590.97,6419.94 h60
  text "3.94mil (0.100mm)" at 5690.65,6419.94 h60
  text "10" at -131.69,6269.94 h60
  text "35.04mil (0.890mm)" at 293.21,6269.94 h60
  text "PTH" at 1417.88,6269.94 h60
  text "3.00mil (0.076mm)" at 2070.71,6269.94 h60
  text "3.00mil (0.076mm)" at 3257.36,6269.94 h60
  text "-" at 4590.97,6269.94 h60
  text "-" at 5690.65,6269.94 h60
  text "20" at -136.69,6119.94 h60
  text "35.43mil (0.900mm)" at 293.21,6119.94 h60
  text "PTH" at 1417.88,6119.94 h60
  text "-" at 4590.97,6119.94 h60
  text "-" at 5690.65,6119.94 h60
  text "3" at -106.7,5969.94 h60
  text "40.00mil (1.016mm)" at 303.21,5969.94 h60
  text "PTH" at 1417.88,5969.94 h60
  text "-" at 4590.97,5969.94 h60
  text "-" at 5690.65,5969.94 h60
  text "23" at -136.69,5819.94 h60
  text "40.16mil (1.020mm)" at 303.21,5819.94 h60
  text "PTH" at 1417.88,5819.94 h60
  text "-" at 4590.97,5819.94 h60
  text "-" at 5690.65,5819.94 h60
  text "6" at -106.7,5669.94 h60
  text "45.28mil (1.150mm)" at 303.21,5669.94 h60
  text "NPTH" at 1417.88,5669.94 h60
  text "3.00mil (0.076mm)" at 2070.71,5669.94 h60
  text "3.00mil (0.076mm)" at 3257.36,5669.94 h60
  text "-" at 4590.97,5669.94 h60
  text "-" at 5690.65,5669.94 h60
  text "2" at -106.7,5519.94 h60
  text "51.18mil (1.300mm)" at 308.2,5519.94 h60
  text "PTH" at 1417.88,5519.94 h60
  text "29.53mil (0.750mm)" at 4590.97,5519.94 h60
  text "-21.65mil (-0.550mm)" at 5690.65,5519.94 h60
  text "4" at -106.7,5369.94 h60
  text "66.93mil (1.700mm)" at 298.21,5369.94 h60
  text "PTH" at 1417.88,5369.94 h60
  text "-" at 4590.97,5369.94 h60
  text "-" at 5690.65,5369.94 h60
  text "3" at -106.7,5219.94 h60
  text "102.99mil (2.616mm)" at 273.22,5219.94 h60
  text "PTH" at 1417.88,5219.94 h60
  text "-" at 4590.97,5219.94 h60
  text "-" at 5690.65,5219.94 h60
  text "4" at -106.7,5069.94 h60
  text "127.95mil (3.250mm)" at 268.22,5069.94 h60
  text "NPTH" at 1417.88,5069.94 h60
  text "-" at 4590.97,5069.94 h60
  text "-" at 5690.65,5069.94 h60
  text "2" at -106.7,4919.94 h60
  text "127.95mil (3.250mm)" at 268.22,4919.94 h60
  text "PTH" at 1417.88,4919.94 h60
  text "-" at 4590.97,4919.94 h60
  text "-" at 5690.65,4919.94 h60
  text "4" at -106.7,4769.94 h60
  text "159.00mil (4.039mm)" at 268.22,4769.94 h60
  text "NPTH" at 1417.88,4769.94 h60
  text "3.00mil (0.076mm)" at 2070.71,4769.94 h60
  text "3.00mil (0.076mm)" at 3257.36,4769.94 h60
  text "-" at 4590.97,4769.94 h60
  text "-" at 5690.65,4769.94 h60
  text "939 Total" at -331.62,4619.94 h60
  text "Slot definitions :" at -837.5,4474.97 h60
  text "Routed Path Length" at 195.19,4474.97 h60
  text "= Calculated from tool start centre position to tool end centre position." at 1297.86,4474.97 h60
  text "Hole Length" at 195.19,4374.99 h60
  text "= Routed Path Length + Tool Size = Slot length as defined in the PCB layout" at 887.99,4374.99 h60
  text ".Layer_Name" at -423.89,-2614.75 h60
M17 Embedded Cavity:
  text ".Layer_Name" at -423.89,-2614.75 h60
M18 Embedded Assembly:
  text ".Layer_Name" at -471,-2575 h60
M19 Embedded Keepout:
  text ".Layer_Name" at -427,-2583 h60
SOM_CONN:
  drawing of 2624 lines, arcs and shapes, not listed
  text "j4" at 980.05,1760 h40 r90
  text "j3" at 2131.28,879.25 h40 r90
  text "J2" at -132.27,868.64 h40 r90
  text "j1" at 972.22,148.68 h40 r90
DXF_PROC110A_BRD_TOP:
  drawing of 19728 lines, arcs and shapes, not listed
DXF_PROC110A_BRD_BTM:
  drawing of 19305 lines, arcs and shapes, not listed
DXF_PROC167A_BRD_BTM:
  drawing of 560 lines, arcs and shapes, not listed
  text "6" at -3069.53,-2137.67 h20
  text "4" at -3176.53,-2177.67 h20
  text "3" at -3145.53,-2258.01 h20
  text "47" at -3559,-2492.01 h15
  text "48" at -3773,-2509.01 h15
  text "2" at -3782,-2882.51 h15
  text "3" at -2983.5,-3159.01 h20
  text "3" at -3264.19,-3160.1 h20
  text "3" at -3122.5,-3160.01 h20
  text "2" at -3179.5,-3196.01 h20
  text "2" at -2906.87,-3195.76 h20
  text "2" at -3042.55,-3196.76 h20
DXF_PROC195E1_PCB_BTM_COMP:
  drawing of 2808 lines, arcs and shapes, not listed
DXF_OSPI_ADDON BRD:
  circle w4: c248.97,1383.25 r54
  circle w4: c248.97,1383.25 r116
  circle w4: c248.97,637.58 r116
  circle w4: c248.97,637.58 r54
  circle w1: c139.23,922.93 r13.78
  lines w1: 153.01,922.93 246.71,922.93
  lines w6: -360.02,487.58 413.54,487.58 413.54,1533.25 -360.02,1533.25 -360.02,487.58

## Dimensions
2132.45,-267.85 to 2244,-738 on M2 Board Dimensions
1994.95,-377.97 to 2171.95,-377.97 on M2 Board Dimensions
2743.26,-133.97 to 2092.95,-133.97 on M2 Board Dimensions
899.06,-369.97 to 946.06,-613.97 on M2 Board Dimensions
-70.05,-377.97 to -70.05,-613.97 on M2 Board Dimensions
2743.26,-133.97 to 2743.26,-609.97 on M2 Board Dimensions
901.05,-418.09 to 750,-418.09 on M2 Board Dimensions
3738.54,-609.97 to 2743.26,-609.97 on M2 Board Dimensions
946.06,-613.97 to 1994.95,-613.97 on M2 Board Dimensions
852.06,-613.97 to -70.05,-613.97 on M2 Board Dimensions
852.06,-613.97 to 946.06,-613.97 on M2 Board Dimensions
3738.54,-377.87 to 3738.54,-609.97 on M2 Board Dimensions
